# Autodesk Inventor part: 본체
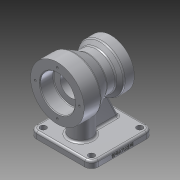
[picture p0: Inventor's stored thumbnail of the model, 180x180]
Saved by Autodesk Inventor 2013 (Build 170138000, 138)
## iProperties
Created: 2019-01
Part Number: 본체
Material: 알루미늄 6061
Document SubType Name: Modeling
Designer: Administrator
Density: 2.71 g/cm^3
Mass: 902.144 g
Surface Area: 600.963 cm^2
Volume: 332.894 cm^3
Author: Administrator
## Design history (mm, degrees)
sketch "스케치1"
  geometry: L1 (-30, 0)-(50, 0); L2 (-30, 0)-(-30, 26); L3 (-30, 40)-(-5, 40); L4 (-5, 40)-(15.785, 28); L5 (15.785, 28)-(29.126, 28); L6 (29.126, 28)-(35, 35); L7 (35, 35)-(50, 35); L8 (50, 35)-(50, 20); L9 (-30, 26)-(-10, 26); L10 (-10, 26)-(-10, 16); L11 (-10, 16)-(33, 16); L12 (33, 16)-(33, 20); L13 (33, 20)-(50, 20); L14 (-30, 26)-(-30, 40); L15 (50, 20)-(50, 0); 1 further point
  constraints: 30 end point, 9 perpendicular, 7 parallel, 1 horizontal, 1 point on line
  dimensions: "d0" = 80 distance of L1.start L1.end; "d2" = 80 diameter of L3 L1; "d3" = 30 distance of L1.start point (0, 0); "d4" = 25 distance of L3.start L3.end; "d5" = 52 diameter of L9 L1; "d6" = 20 distance of L2.end L9.end; "d7" = 32 diameter of L11 L1; "d8" = 56 diameter of L5 L1; "d9" = 30 deg angle of L5 L4; "d10" = 50 deg angle of L5 L6; "d11" = 70 diameter of L7 L1; "d12" = 15 distance of L6.end L7.end; "d13" = 40 diameter of L13 L1; "d14" = 17 distance of L12.end L8.end; "d15" = 43 distance of L10.end L11.end
revolve "회전1" sketch "스케치1" stored, may be unused: angle "d16" = 90 deg
sketch "스케치2"
  geometry: C1 r 40 at (0, 0) reference; 1 further point
  constraints: 1 vertical alignment
  dimensions: "d17" = 33 distance of C1.centre point (0, 33)
hole "구멍1" sketch "스케치2" at (0, 33) diameter "d18" = 3.242; stored, may be unused: countersink angle "d22" = 90 deg, drill point angle "d24" = 118 deg; dims "d19" = 9, "d20" = 4, "d21" = 2, "d23" = 11
sketch "스케치3"
  geometry: C1 r 20 at (0, 0) reference; 1 further point
  constraints: 1 vertical alignment
  dimensions: "d28" = 27.5 distance of C1.centre point (0, 27.5)
hole "구멍2" sketch "스케치3" at (0, 27.5) diameter "d29" = 3.242; stored, may be unused: countersink angle "d33" = 90 deg, drill point angle "d35" = 118 deg; dims "d30" = 9, "d31" = 4, "d32" = 2, "d34" = 11
sketch "스케치4"
  geometry: L1 (-25, -70)-(67, -70); L2 (67, -70)-(67, -80); L3 (67, -80)-(-25, -80); L4 (-25, -80)-(-25, -70); 1 further point
  constraints: 8 end point, 2 parallel, 1 horizontal, 1 perpendicular
  dimensions: "d39" = 92 distance of L1.start L1.end; "d41" = 10 distance of L3.end L1.start; "d42" = 80 distance from line of L3 point (0, 0); "d67" = 25 distance from line of point (0, 0) L4
extrude "돌출1" join sketch "스케치4" stored distance "d44" = 92; taper "d45" = 0 deg
fillet "모깎기1" dims "d46" = 10
sketch "스케치5"
  geometry: A1 r 10 centre (72, -10) between (82, -10) and (72, 0) reference; A2 r 10 centre (0, -10) between (0, 0) and (-10, -10) reference; A3 r 10 centre (0, -82) between (-10, -82) and (0, -92) reference; A4 r 10 centre (72, -82) between (72, -92) and (82, -82) reference; 5 further points
  constraints: 4 coincident
hole "구멍3" sketch "스케치5" at (0, -10), (0, -82), (72, -82), (72, -10) diameter "d47" = 9; stored, may be unused: countersink angle "d51" = 90 deg, drill point angle "d53" = 118 deg; dims "d48" = 9, "d49" = 4, "d50" = 2, "d52" = 11
sketch "스케치6"
  geometry: L1 (-10, -10)-(-10, -82) reference; L2 (72, -92)-(0, -92) reference; C1 r 16 at (20, -46); 1 further point
  constraints: 1 centre point
  dimensions: "d68" = 32 diameter of C1; "d70" = 30 distance from line of L1 C1.centre; "d71" = 46 distance from line of C1.centre L2
extrude "돌출2" join sketch "스케치6" stored distance "d56" = 0; taper "d57" = 0 deg
sketch "스케치7"
  geometry: L1 (42.078, -37.999)-(57, -70); L2 (57, -70)-(-15, -70) reference; L3 (67, -80)-(67, -70) reference; L4 (57, -70)-(67, -70) reference; 1 further point
  constraints: 2 end point, 1 point on line
  dimensions: "d58" = 25 deg angle of L1 L3; "d59" = 10 distance from line of L3 L1.end
feature "리브1" sketch "스케치7" dims "d60" = 1, "d61" = 10, "d62" = 0, "d63" = 0, "d64" = 1, "d65" = 1
fillet "모깎기3" dims "d72" = 3
fillet "모깎기4" dims "d73" = 3
fillet "모깎기5" dims "d74" = 3
fillet "모깎기6" dims "d75" = 3
fillet "모깎기7" dims "d76" = 1
fillet "모깎기8" dims "d77" = 0.6
chamfer "모따기1" distance "d78" = 1; stored, may be unused: second distance "d79" = 2, angle "d80" = 45 deg
sketch "스케치8"
  geometry: L1 (-15, -80)-(57, -80) reference; L2 (-25, -73)-(-25, -80) reference; 2 further points
  constraints: 1 other
  dimensions: "d81" = 4 distance from line of L1 point (21, -76); "d82" = 46 distance from line of L2 point (21, -76)
feature "엠보싱1" sketch "스케치8" dims "d17" = 33, "d83" = 0.5, "d84" = 0
node "솔리드1"
pattern_circular "원형 패턴1" dims angle "d26" = 360 deg
pattern_circular "원형 패턴2" dims angle "d37" = 360 deg
